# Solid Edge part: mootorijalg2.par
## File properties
Author: Mac
Template: Normal.par
Last saved by: Mac
Revision: 11
Application: Solid Edge
Material: Aluminum, 1060
Face Style: Aluminum
Fill Style: ANSI38(Aluminum)
Virtual Style: Polished aluminum
Coef. of Thermal Exp: 2.3e-05
Thermal Conductivity: 221.0
Specific Heat: 920.0
Modulus of Elasticity: 68947570000.0
Poission's Ratio: 0.33
Yield Stress: 27579028.0
Ultimate Stress: 68947570.0
Elongation: 0.0
Density: 2712,000 kg/m^3
Accuracy: 0,010
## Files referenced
(..\..\..\Copy of copy of paat3\Asm15.asm
EC:\Documents and Settings\Mac\Desktop\Copy of copy of paat3\Asm15.asm
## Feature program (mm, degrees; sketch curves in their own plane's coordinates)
sketch for "unnamed Protrusion 1" plane through (0, -5.9734, 8.0273) normal (-1, 0, 0) x-axis (0, -1, 0)
extrude "unnamed Protrusion 1" add finite 0.4 along -normal
sketch for "unnamed Protrusion 2" plane through (0, 8.4266, 0) normal (0, -1, 0) x-axis (1, 0, 0)
  line (-1.3928, 10.396) -> (-3.7545, 10.898)
  arc centre (-4.5561, 7.1268) radius 3.8555 from (-3.7545, 10.898) to (-8.3274, 7.9284) ccw
  line (-9.0303, 4.6215) -> (-8.3274, 7.9284)
  line (-9.0303, 4.6215) -> (-2.8973, 3.3179)
  line (-1.3928, 10.396) -> (-2.8973, 3.3179)
extrude "unnamed Protrusion 2" add to key point symmetric
draft "Draft_6"  Angles1 = 3 deg
draft "Draft_7"  Angles1 = 3 deg
sketch for "ExtrudedProtrusion_7" plane through (-5.9638, 8.4266, 3.9697) normal (-0.207912, 0, -0.978148) x-axis (-0.978148, 0, 0.207912)
  line (4.6048, -2.4688) -> (-3.135, -2.0009)
  line (-3.135, 2.0009) -> (-3.135, -2.0009)
  line (4.6048, 2.4688) -> (-3.135, 2.0009)
  arc centre (4.635, 1.9697) radius 0.5 from (5.135, 1.9697) to (4.6048, 2.4688) ccw
  line (5.135, 1.9697) -> (5.135, -1.9697)
  arc centre (4.635, -1.9697) radius 0.5 from (5.135, -1.9697) to (4.6048, -2.4688) cw
extrude "ExtrudedProtrusion_7" add finite 0.1 along +normal
fillet "Round_7" radius 0.5
sketch for "ExtrudedProtrusion_8" plane through (-6.9627, 8.4266, 4.0798) normal (-0.207912, 0, -0.978148) x-axis (-0.976365, -0.060349, 0.207533)
  arc centre (-1.5594, -0.0943) radius 2.0009 from (-1.5438, 1.9065) to (-1.4387, -2.0915) ccw
  arc centre (-1.2864, -0.0871) radius 2.0102 from (-1.5438, 1.9065) to (-1.4387, -2.0915) cw
extrude "ExtrudedProtrusion_8" add finite 0.2 along +normal
sketch for "ExtrudedProtrusion_9" plane through (-5.6142, 8.4173, 3.5887) normal (-0.207912, 0, -0.978148) x-axis (-0.978148, 0, 0.207912)
  line (-2.7138, -1.9916) -> (5.026, -2.4595)
  arc centre (5.0562, -1.9604) radius 0.5 from (5.026, -2.4595) to (5.5562, -1.9604) ccw
  line (5.5562, -1.9604) -> (5.5562, 1.979)
  arc centre (5.0562, 1.979) radius 0.5 from (5.5562, 1.979) to (5.026, 2.4781) ccw
  line (5.026, 2.4781) -> (-2.7138, 2.0102)
  line (-2.7138, 2.0102) -> (-2.7138, -1.9916)
extrude "ExtrudedProtrusion_9" add finite 0.15 along +normal
sketch for "ExtrudedCutout_1" plane through (-7.0355, 8.4266, 3.7374) normal (-0.207912, 0, -0.978148) x-axis (0.976365, -0.060349, -0.207533)
extrude "ExtrudedCutout_1" cut finite 0.1 along -normal
sketch for "unnamed Cutout 1" plane through (0, 8.4266, 8.5708) normal (-1, 0, 0) x-axis (0, 0, 1)
extrude "unnamed Cutout 1" cut through along -normal
fillet "unnamed Round 1"
thinwall "Thinwall_13"  Thickness = 0.05 mm
lofted protrusion "unnamed LoftedProtrusion 1"
lofted cutout "unnamed LoftedCutout 1"
sketch for "ExtrudedProtrusion_12" plane through (-7.0506, 8.4245, -1.3711) normal (-0.207912, 0, -0.978148) x-axis (0.978148, 0, -0.207912)
extrude "ExtrudedProtrusion_12" add finite 0.3796 along +normal
sketch for "unnamed Cutout 2" plane through (-6.693, 10.6614, 4.0736) normal (0.059031, 0.998177, -0.012547) x-axis (0.976365, -0.060349, -0.207533)
extrude "unnamed Cutout 2" cut finite 8.6725 along -normal
sketch for "ExtrudedCutout_4" plane through (-11.0645, 8.4266, 4.6705) normal (-0.978148, 0, 0.207912) x-axis (0, 1, 0)
extrude "ExtrudedCutout_4" cut finite 10.4554 along -normal
sketch for "ExtrudedProtrusion_13" plane through (-3.9, 8.4266, 6.9233) normal (0.978148, 0, -0.207912) x-axis (0, -1, 0)
extrude "ExtrudedProtrusion_13" add finite 1.768 along -normal
fillet "unnamed Round 2"
sketch for "unnamed Protrusion 3" plane through (-6.9749, 8.4266, 0.961) normal (-0.978148, 0, 0.207912) x-axis (0, -1, 0)
extrude "unnamed Protrusion 3" add to key point along +normal
sketch for "ExtrudedProtrusion_15" #1 plane through (-2.2074, 8.4266, 6.5635) normal (0.978148, 0, -0.207912) x-axis (0, 1, 0)
sketch for "ExtrudedProtrusion_15" #2 plane through (-2.2074, 8.4266, 6.5635) normal (0.978148, 0, -0.207912) x-axis (0, 1, 0)
extrude "ExtrudedProtrusion_15" add finite 1.4 along +normal
sketch for "unnamed Cutout 3" #1 plane through (-0.916, 8.4266, 9.2723) normal (0.207912, 0, 0.978148) x-axis (0, 1, 0)
  line (-0.7, 0.7) -> (-0.4893, -0.3028)
  line (0.7, 0.7) -> (0.4893, -0.3028)
  line (1.0657, 0.7) -> (0.7, 0.7)
  line (1.0657, -0.8394) -> (1.0657, 0.7)
  line (-0.9064, -0.8394) -> (1.0657, -0.8394)
  line (-0.9064, 0.7) -> (-0.9064, -0.8394)
  line (-0.7, 0.7) -> (-0.9064, 0.7)
sketch for "unnamed Cutout 3" #2 plane through (-0.916, 8.4266, 9.2723) normal (0.207912, 0, 0.978148) x-axis (0, 1, 0)
extrude "unnamed Cutout 3" cut along +normal
sketch for "unnamed Protrusion 4" #1 plane through (-6.0409, 6.2251, 9.4132) normal (0.544639, 0, -0.838671) x-axis (0.838671, 0, 0.544639)
extrude "unnamed Protrusion 4" add along +normal
Other named dimensions: "OffsetSurface_1": Distance = 0.02 mm | "ExtrudedSurface_2": FiniteDepth = 12.4503 mm
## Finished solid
Body 1: sheet body, 1 face, 4 edges, 4 vertices.
  Faces by surface: plane 1
  Edges by curve: line 4
Body 2: sheet body, 1 face, 4 edges, 4 vertices.
  Faces by surface: cylinder 1
  Edges by curve: ellipse 2, line 2
Body 3: solid body, 210 faces, 517 edges, 323 vertices, 1 internal void.
  Faces by surface: plane 93, cylinder 63, swept 31, spline 10, blend 8, sphere 4, torus 1
  Edges by curve: line 242, circle 127, intersection 98, ellipse 27, spline 12, curve on surface 11
Bounding box of the edges (mm; curved faces can reach further): 11.452 x 12.450 x 12.694, from (-11.6837, 0, -1.6912) to (-0.2313, 12.4503, 11.0023).
Cylindrical faces by radius (mm): R0.0434 x2, R0.2 x1, R0.3 x2, R0.45 x9, R0.5 x14, R0.55 x1, R0.7427 x5, R0.8 x1, R0.85 x1, R1.2034 x4, R1.9509 x1, R1.9602 x1, R2.0009 x1, R2.0102 x1, R2.0417 x1, R2.0602 x2, R2.0795 x1, R2.0917 x1, R2.1102 x2, R2.1295 x1, R3.8055 x3, R3.8555 x3, R3.8755 x6
Toroidal faces (ring radius, tube radius in mm): R0.4427 r0.3 x1
Spherical faces by radius (mm): R0.45 x2, R0.5 x2
Planar faces by outward normal: +y 6, -y 12, oblique 75
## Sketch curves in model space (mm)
line (-8.3274, 0, 7.9284) -> (-3.7545, 0, 10.898)
arc centre (-7.0248, 7.3732, -1.3765) radius 1.2034 from (-7.0248, 8.5766, -1.3765) through (-7.3187, 8.5385, -1.3141) to (-7.5939, 8.4266, -1.2556)
arc centre (-7.0248, 7.3732, -1.3765) radius 1.2034 from (-7.0248, 8.5766, -1.3765) through (-6.7725, 8.5486, -1.4302) to (-6.5319, 8.466, -1.4813)
arc centre (-6.5497, 8.4266, -1.4775) radius 0.0434 from (-6.5319, 8.3872, -1.4813) through (-6.5072, 8.4266, -1.4866) to (-6.5319, 8.466, -1.4813)
arc centre (-7.0248, 9.4799, -1.3765) radius 1.2034 from (-7.0248, 8.2766, -1.3765) through (-6.7725, 8.3045, -1.4302) to (-6.5319, 8.3872, -1.4813)
arc centre (-7.0248, 9.4799, -1.3765) radius 1.2034 from (-7.0248, 8.2766, -1.3765) through (-7.3187, 8.3147, -1.3141) to (-7.5939, 8.4266, -1.2556)
arc centre (-7.0248, 7.3732, -1.3765) radius 1.1034 from (-7.346, 8.4266, -1.3083) through (-7.1873, 8.464, -1.342) to (-7.0248, 8.4766, -1.3765)
arc centre (-7.0248, 7.3732, -1.3765) radius 1.1034 from (-7.0248, 8.4766, -1.3765) through (-6.8624, 8.464, -1.4111) to (-6.7036, 8.4266, -1.4448)
arc centre (-7.0248, 9.4799, -1.3765) radius 1.1034 from (-6.7036, 8.4266, -1.4448) through (-6.8624, 8.3891, -1.4111) to (-7.0248, 8.3766, -1.3765)
arc centre (-7.0248, 9.4799, -1.3765) radius 1.1034 from (-7.0248, 8.3766, -1.3765) through (-7.1873, 8.3891, -1.342) to (-7.346, 8.4266, -1.3083)
arc centre (-5.3963, 9.5877, 0.322) radius 1.8602 from (-5.3963, 7.7275, 0.322) through (-6.1851, 7.9114, 0.4896) to (-6.8179, 8.4266, 0.6241)
arc centre (-5.3963, 9.5693, 0.322) radius 1.8417 from (-5.3963, 7.7275, 0.322) through (-5.0337, 7.7652, 0.2449) to (-4.6859, 7.8768, 0.171)
arc centre (-4.9173, 8.4282, 0.2202) radius 0.6 from (-4.6927, 8.9825, 0.1724) through (-4.3305, 8.432, 0.0954) to (-4.6859, 7.8768, 0.171)
arc centre (-5.3963, 7.2461, 0.322) radius 1.8795 from (-5.3963, 9.1256, 0.322) through (-5.0376, 9.0895, 0.2457) to (-4.6927, 8.9825, 0.1724)
arc centre (-5.3963, 7.2654, 0.322) radius 1.8602 from (-5.3963, 9.1256, 0.322) through (-6.1851, 8.9418, 0.4896) to (-6.8179, 8.4266, 0.6241)
arc centre (-5.3963, 7.2654, 0.322) radius 1.7602 from (-6.6903, 8.4266, 0.597) through (-6.1066, 8.8689, 0.473) to (-5.3963, 9.0256, 0.322)
arc centre (-5.3963, 7.2461, 0.322) radius 1.7795 from (-5.3963, 9.0256, 0.322) through (-5.0567, 8.9914, 0.2498) to (-4.7301, 8.8901, 0.1804)
arc centre (-4.9173, 8.4282, 0.2202) radius 0.5 from (-4.7301, 8.8901, 0.1804) through (-4.4283, 8.4313, 0.1162) to (-4.7244, 7.9687, 0.1792)
arc centre (-5.3963, 9.5693, 0.322) radius 1.7417 from (-4.7244, 7.9687, 0.1792) through (-5.0534, 7.8632, 0.2491) to (-5.3963, 7.8275, 0.322)
arc centre (-5.3963, 9.5877, 0.322) radius 1.7602 from (-5.3963, 7.8275, 0.322) through (-6.1066, 7.9843, 0.473) to (-6.6903, 8.4266, 0.597)
arc centre (-4.2936, 8.4282, 3.1546) radius 0.9 from (-3.9567, 9.2596, 3.083) through (-3.4133, 8.4339, 2.9675) to (-3.9464, 7.6011, 3.0808)
arc centre (-4.7726, 9.5693, 3.2564) radius 2.1417 from (-4.7726, 7.4275, 3.2564) through (-4.3509, 7.4714, 3.1668) to (-3.9464, 7.6011, 3.0808)
arc centre (-4.7726, 9.5877, 3.2564) radius 2.1602 from (-4.7726, 7.4275, 3.2564) through (-5.7887, 7.6937, 3.4724) to (-6.5544, 8.4266, 3.6352)
arc centre (-4.7726, 7.2654, 3.2564) radius 2.1602 from (-4.7726, 9.4256, 3.2564) through (-5.7887, 9.1594, 3.4724) to (-6.5544, 8.4266, 3.6352)
arc centre (-4.7726, 7.2461, 3.2564) radius 2.1795 from (-4.7726, 9.4256, 3.2564) through (-4.3566, 9.3837, 3.168) to (-3.9567, 9.2596, 3.083)
arc centre (-4.7726, 9.5693, 3.2564) radius 2.0417 from (-3.985, 7.693, 3.089) through (-4.3706, 7.5693, 3.171) to (-4.7726, 7.5275, 3.2564)
arc centre (-4.7726, 9.5877, 3.2564) radius 2.0602 from (-4.7726, 7.5275, 3.2564) through (-5.7139, 7.7661, 3.4565) to (-6.4372, 8.4266, 3.6103)
arc centre (-4.7726, 7.2654, 3.2564) radius 2.0602 from (-6.4372, 8.4266, 3.6103) through (-5.7139, 9.087, 3.4565) to (-4.7726, 9.3256, 3.2564)
arc centre (-4.7726, 7.2461, 3.2564) radius 2.0795 from (-4.7726, 9.3256, 3.2564) through (-4.3757, 9.2856, 3.1721) to (-3.9941, 9.1673, 3.091)
arc centre (-4.2936, 8.4282, 3.1546) radius 0.8 from (-3.9941, 9.1673, 3.091) through (-3.5111, 8.4332, 2.9883) to (-3.985, 7.693, 3.089)
arc centre (0, 4.2366, 8.1064) radius 1.34 from (0, 5.5766, 8.1064) through (0, 5.5235, 8.4798) to (0, 5.3685, 8.8235)
arc centre (0, 8.4266, 10.7608) radius 3.62 from (0, 5.3685, 8.8235) through (0, 8.4266, 14.3808) to (0, 11.4846, 8.8235)
arc centre (0, 12.6166, 8.1064) radius 1.34 from (0, 11.4846, 8.8235) through (0, 11.3296, 8.4798) to (0, 11.2766, 8.1064)
line (0, 11.2766, 8.1064) -> (0, 11.2766, 5.6108)
arc centre (0, 8.4266, 5.6108) radius 2.85 from (0, 11.2766, 5.6108) through (0, 8.3421, 2.762) to (0, 5.5766, 5.6108)
line (0, 5.5766, 5.6108) -> (0, 5.5766, 8.1064)
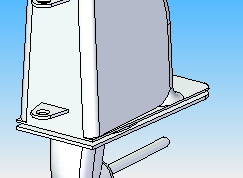
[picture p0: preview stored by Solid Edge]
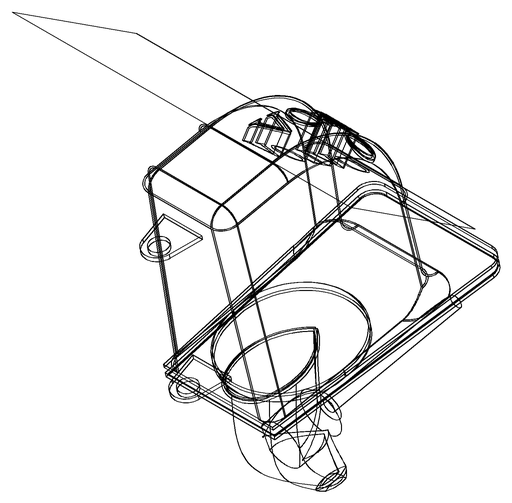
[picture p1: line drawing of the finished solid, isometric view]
